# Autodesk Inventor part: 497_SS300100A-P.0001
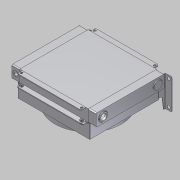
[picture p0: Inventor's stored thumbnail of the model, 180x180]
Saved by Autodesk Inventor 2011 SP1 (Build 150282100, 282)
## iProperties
Created: 2016-01
Document SubType Name: Modeling
Designer: romansazanov
Density: 1 g/cm^3
Author: romansazanov
Стандарт преобразования: STEP AP203
Имя файла: SS300100A-P.stp
Препроцессор: THINKDESIGN
Постпроцессор: Build: 282, Release: 2011 SP1 - Date: Thu 08/05/2010
Отправленные единицы: миллиметр
Неопределенность: 0.001
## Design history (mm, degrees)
feature "БазТело1"
feature "БазТело2"
feature "БазТело3"
feature "БазТело4"
feature "БазТело5"
feature "БазТело6"
feature "БазТело7"
feature "БазТело8"
feature "БазТело9"
feature "БазТело10"
feature "БазТело11"
feature "БазТело12"
feature "БазТело13"
feature "БазТело14"
feature "БазТело15"
feature "БазТело16"
feature "БазТело17"
feature "БазТело18"
feature "БазТело19"
feature "БазТело20"
feature "БазТело21"
feature "БазТело22"
feature "БазТело23"
feature "БазТело24"
feature "БазТело25"
feature "БазТело26"
feature "БазТело27"
feature "БазТело28"
feature "БазТело29"
feature "БазТело30"
feature "БазТело31"
feature "БазТело32"
feature "БазТело33"
feature "БазТело34"
feature "БазТело35"
feature "БазТело36"
feature "БазТело37"
feature "БазТело38"
feature "БазТело39"
feature "БазТело40"
feature "БазТело41"
feature "БазТело42"
feature "БазТело43"
feature "БазТело44"
feature "БазТело45"
feature "БазТело46"
feature "БазТело47"
feature "БазТело48"
feature "БазТело49"
feature "БазТело50"
feature "БазТело51"
feature "БазТело52"
feature "БазТело53"
feature "БазТело54"
feature "БазТело55"
feature "БазТело56"
feature "БазТело57"
feature "БазТело58"
feature "БазТело59"
feature "БазТело60"
feature "БазТело61"
feature "БазТело62"
feature "БазТело63"
feature "БазТело64"
feature "БазТело65"
node "None"
node "None_1"
node "None_2"
node "None_3"
node "None_4"
node "None_5"
node "None_6"
node "None_7"
node "None_8"
node "None_9"
node "None_10"
node "None_11"
node "None_12"
node "None_13"
node "None_14"
node "None_15"
node "None_16"
node "None_17"
node "None_18"
node "None_19"
node "None_20"
node "None_21"
node "None_22"
node "None_23"
node "None_24"
node "None_25"
node "None_26"
node "None_27"
node "None_28"
node "None_29"
node "None_30"
node "None_31"
node "None_32"
node "None_33"
node "None_34"
node "None_35"
node "None_36"
node "None_37"
node "None_38"
node "None_39"
node "None_40"
node "None_41"
node "None_42"
node "None_43"
node "None_44"
node "None_45"
node "None_46"
node "None_47"
node "None_48"
node "None_49"
node "None_50"
node "None_51"
node "None_52"
node "None_53"
node "None_54"
node "None_55"
node "None_56"
node "None_57"
node "None_58"
node "None_59"
node "None_60"
node "None_61"
node "None_62"
node "None_63"
node "None_64"
